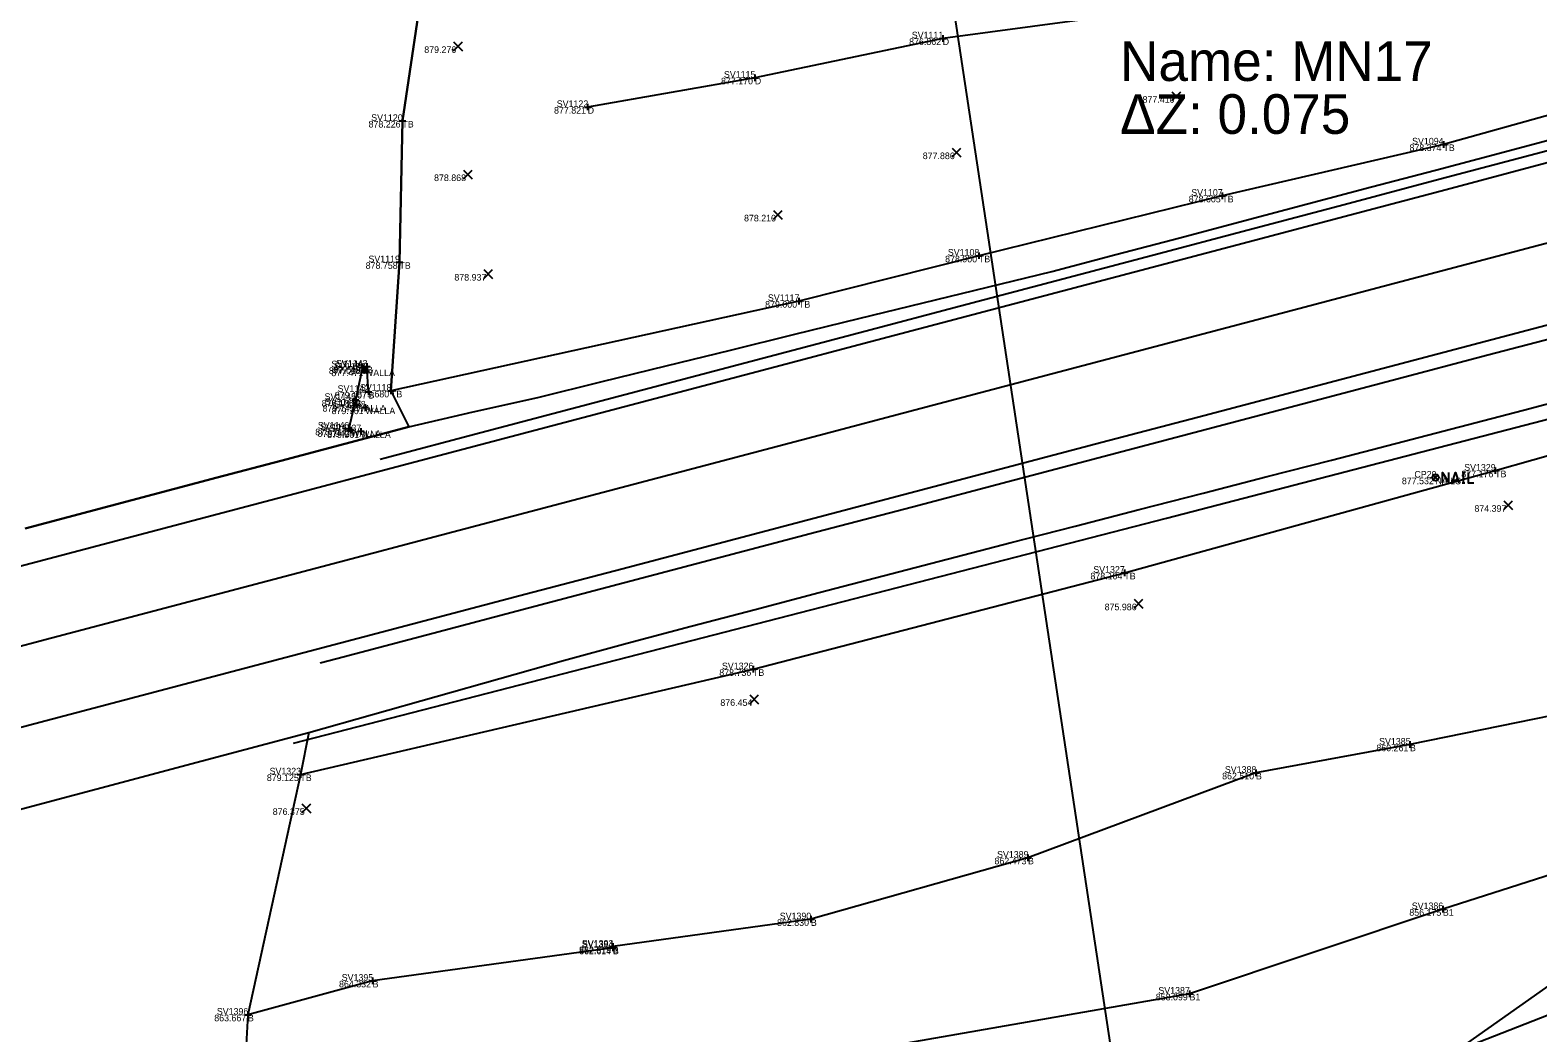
# Model space of a CAD drawing. Extents: x 2125299 to 2129212, y 713100 to 714300.
# Drawn here: x 2128033.5 to 2128261.4, y 713835.6 to 713987.2 of the extents above; entities that cross this region are included whole.
import ezdxf

# ---------------------------------------------------------------- set-up
doc = ezdxf.new("R2010")
doc.units = 0
for name, color, linetype in [('_CIVIL_CONSTRUCTION', 7, 'Continuous'), ('Default', 7, 'Continuous'), ('DR_X_Ditch', 7, 'Continuous'), ('DT_X_Void', 7, 'Continuous'), ('PV_X_EOP', 7, 'Continuous'), ('PV_X_Shoulder_Rumble_Strip', 7, 'Continuous'), ('RD_X_Fence', 7, 'Continuous'), ('RW_P_Esmt_TMP', 7, 'Continuous'), ('RW_X_CL_100_Curve_Data', 7, 'Continuous'), ('RW_X_Esmt_CH', 7, 'Continuous'), ('RW_X_Fee_WL', 7, 'Continuous'), ('SC_Scratch1', 7, 'Continuous'), ('SC_Scratch2', 7, 'Continuous'), ('SV_X_Break_Lines', 7, 'Continuous'), ('SV_X_Mon_Cells_Found', 7, 'Continuous'), ('SV_X_Text_Elevation', 7, 'Continuous'), ('SV_X_Text_Name', 7, 'Continuous'), ('SV_X_Top_of_Bank', 7, 'Continuous'), ('UT_X_Overhead_Telecom_FO', 7, 'Continuous')]:
    doc.layers.add(name, color=color, linetype=linetype)

msp = doc.modelspace()

# ---------------------------------------------------------------- linework, layer by layer
at = {"layer": '_CIVIL_CONSTRUCTION'}
msp.add_lwpolyline([(2128022.26, 713891.52), (2128036.76, 713895.35), (2128051.26, 713899.19), (2128065.76, 713903.02), (2128080.27, 713906.86), (2128094.77, 713910.69), (2128109.27, 713914.52), (2128123.77, 713918.35), (2128138.28, 713922.18), (2128152.78, 713926), (2128167.28, 713929.83), (2128181.79, 713933.66), (2128196.29, 713937.49), (2128210.79, 713941.32), (2128225.3, 713945.14), (2128239.8, 713948.97), (2128254.3, 713952.8), (2128268.81, 713956.63)], dxfattribs=at)
at = {"layer": 'Default'}
msp.add_lwpolyline([(2128027.32, 713868.17), (2128036.98, 713870.74), (2128046.65, 713873.31), (2128056.31, 713875.88), (2128065.98, 713878.44), (2128075.64, 713881.03), (2128074.37, 713874.69), (2128066.44, 713838.36), (2128065.59, 713822.89), (2128050.49, 713795.43), (2128103.72, 713804.69), (2128133.83, 713809.76), (2128180.68, 713818.15), (2128213.09, 713823.85), (2128249.08, 713832.87), (2128285.01, 713846.97)], dxfattribs=at)
at = {"layer": 'DR_X_Ditch'}
msp.add_lwpolyline([(2128539.96, 714065.48), (2128533.93, 714063.76), (2128504.91, 714054.76), (2128447.02, 714038.39), (2128399.37, 714025.09), (2128341.85, 714009.81), (2128283.6, 713994.68), (2128242.74, 713988.86), (2128205.78, 713990.56), (2128171.48, 713986), (2128143.07, 713980.05), (2128117.8, 713975.62)], dxfattribs=at)
at = {"layer": 'DT_X_Void'}
msp.add_lwpolyline([(2128091.1, 714003.39), (2128093.27, 713996.96), (2128089.79, 713973.52), (2128089.34, 713952.15), (2128088.07, 713932.71), (2128090.77, 713927.26), (2128081.1, 713924.7), (2128071.43, 713922.14), (2128061.77, 713919.58), (2128052.1, 713917.02), (2128042.43, 713914.46), (2128032.77, 713911.9)], dxfattribs=at)
at = {"layer": 'PV_X_EOP'}
for points in [[(2128032.77, 713911.9), (2128042.43, 713914.46), (2128052.1, 713917.02), (2128061.77, 713919.58), (2128071.43, 713922.14), (2128081.1, 713924.7), (2128090.77, 713927.26), (2128100.51, 713929.52), (2128110.27, 713931.7), (2128119.98, 713934.09), (2128129.69, 713936.48), (2128139.4, 713938.87), (2128149.11, 713941.25), (2128158.82, 713943.63), (2128168.53, 713946.01), (2128178.25, 713948.39), (2128187.96, 713950.77), (2128197.63, 713953.31), (2128207.3, 713955.86), (2128216.97, 713958.42), (2128226.63, 713960.98), (2128236.3, 713963.53), (2128245.97, 713966.09), (2128255.64, 713968.65), (2128265.3, 713971.22)], [(2128027.32, 713868.17), (2128036.98, 713870.74), (2128046.65, 713873.31), (2128056.31, 713875.88), (2128065.98, 713878.44), (2128075.64, 713881.03), (2128085.26, 713883.75), (2128094.88, 713886.47), (2128104.51, 713889.2), (2128114.13, 713891.92), (2128123.77, 713894.56), (2128133.44, 713897.11), (2128143.11, 713899.65), (2128152.78, 713902.2), (2128162.46, 713904.74), (2128172.14, 713907.24), (2128181.82, 713909.74), (2128191.5, 713912.24), (2128201.18, 713914.74), (2128210.87, 713917.24), (2128220.55, 713919.74), (2128230.23, 713922.24), (2128239.91, 713924.74), (2128249.6, 713927.24), (2128259.27, 713929.78), (2128268.94, 713932.34)]]:
    msp.add_lwpolyline(points, dxfattribs=at)
at = {"layer": 'PV_X_Shoulder_Rumble_Strip'}
for points in [[(2128086.42, 713922.37), (2128087.17, 713922.56), (2128101.67, 713926.39), (2128116.17, 713930.23), (2128130.67, 713934.06), (2128145.17, 713937.89), (2128159.68, 713941.72), (2128174.18, 713945.55), (2128188.68, 713949.38), (2128203.18, 713953.21), (2128217.68, 713957.05), (2128232.18, 713960.89), (2128246.68, 713964.74), (2128261.18, 713968.58), (2128275.68, 713972.42), (2128290.18, 713976.26), (2128304.68, 713980.1), (2128319.18, 713983.94), (2128333.68, 713987.78)], [(2128077.36, 713891.58), (2128079.87, 713892.24), (2128094.37, 713896.07), (2128108.87, 713899.89), (2128123.38, 713903.71), (2128137.88, 713907.53), (2128152.38, 713911.36), (2128166.89, 713915.18), (2128181.39, 713919), (2128195.9, 713922.83), (2128210.4, 713926.65), (2128224.91, 713930.47), (2128239.41, 713934.29), (2128253.91, 713938.12), (2128268.41, 713941.95)]]:
    msp.add_lwpolyline(points, dxfattribs=at)
at = {"layer": 'RD_X_Fence'}
msp.add_lwpolyline([(2128324.53, 713881.58), (2128301.55, 713867.57), (2128272.2, 713849.2), (2128249.08, 713832.87), (2128213.09, 713823.85), (2128180.68, 713818.15), (2128133.83, 713809.76), (2128103.72, 713804.69), (2128050.49, 713795.43)], dxfattribs=at)
at = {"layer": 'SC_Scratch1'}
msp.add_lwpolyline([(2128073.34, 713879.42), (2128205.29, 713913.45), (2128375.42, 713957.63), (2128480.61, 713986.26)], dxfattribs=at)
at = {"layer": 'SC_Scratch2'}
for points in [[(2128030.06, 713905.67), (2128044.56, 713909.5), (2128059.06, 713913.33), (2128073.57, 713917.16), (2128088.07, 713920.99), (2128102.57, 713924.83), (2128117.07, 713928.66), (2128131.57, 713932.49), (2128146.08, 713936.32), (2128160.58, 713940.15), (2128175.08, 713943.98), (2128189.58, 713947.82), (2128204.09, 713951.65), (2128218.59, 713955.49), (2128233.09, 713959.33), (2128247.59, 713963.17), (2128262.09, 713967.01), (2128276.59, 713970.85), (2128291.09, 713974.69), (2128305.59, 713978.53), (2128320.09, 713982.37), (2128334.59, 713986.21), (2128349.09, 713990.05)], [(2128021.45, 713879.04), (2128035.96, 713882.86), (2128050.46, 713886.69), (2128064.97, 713890.51), (2128079.47, 713894.33), (2128093.98, 713898.16), (2128108.48, 713901.98), (2128122.99, 713905.8), (2128137.49, 713909.62), (2128151.99, 713913.45), (2128166.5, 713917.27), (2128181, 713921.09), (2128195.51, 713924.92), (2128210.01, 713928.74), (2128224.52, 713932.56), (2128239.02, 713936.39), (2128253.53, 713940.21), (2128268.03, 713944.04)]]:
    msp.add_lwpolyline(points, dxfattribs=at)
at = {"layer": 'SV_X_Break_Lines'}
for points in [[(2128084.68, 713932.54), (2128084.42, 713936.37), (2128083.78, 713936.25), (2128082.7, 713931.33), (2128081.71, 713926.98)], [(2128473.37, 713923.91), (2128453.45, 713915.84), (2128410.19, 713893.98), (2128387.41, 713892.53), (2128363.21, 713893.72), (2128345.6, 713896.5), (2128318.82, 713891.26), (2128295.12, 713880.91), (2128274.49, 713885.8), (2128242.12, 713879.2), (2128218.83, 713874.94), (2128184.37, 713862.1), (2128151.55, 713852.79), (2128121.59, 713848.65), (2128121.63, 713848.49), (2128085.29, 713843.49), (2128066.44, 713838.36)], [(2128362.17, 713888.6), (2128349.08, 713887.91), (2128324.53, 713881.58), (2128301.55, 713867.57), (2128295.43, 713864.02), (2128280.27, 713864.93), (2128247.09, 713854.32), (2128208.78, 713841.53), (2128155.39, 713832.17), (2128105.37, 713824.74)]]:
    msp.add_lwpolyline(points, dxfattribs=at)
at = {"layer": 'SV_X_Mon_Cells_Found'}
for p, q in [((2128170.98, 713986), (2128171.98, 713986)), ((2128171.48, 713986.5), (2128171.48, 713985.5)), ((2128171.48, 713986), (2128171.48, 713986)), ((2128142.57, 713980.05), (2128143.57, 713980.05)), ((2128143.07, 713980.55), (2128143.07, 713979.55)), ((2128143.07, 713980.05), (2128143.07, 713980.05)), ((2128117.3, 713975.62), (2128118.3, 713975.62)), ((2128117.8, 713976.12), (2128117.8, 713975.12)), ((2128117.8, 713975.62), (2128117.8, 713975.62)), ((2128089.29, 713973.52), (2128090.29, 713973.52)), ((2128089.79, 713974.02), (2128089.79, 713973.02)), ((2128089.79, 713973.52), (2128089.79, 713973.52)), ((2128247.17, 713970.46), (2128247.17, 713969.46)), ((2128246.67, 713969.96), (2128247.67, 713969.96)), ((2128247.17, 713969.96), (2128247.17, 713969.96)), ((2128213.24, 713962.2), (2128214.24, 713962.2)), ((2128213.74, 713962.7), (2128213.74, 713961.7)), ((2128213.74, 713962.2), (2128213.74, 713962.2)), ((2128088.84, 713952.15), (2128089.84, 713952.15)), ((2128089.34, 713952.65), (2128089.34, 713951.65)), ((2128089.34, 713952.15), (2128089.34, 713952.15)), ((2128176.45, 713953.14), (2128177.45, 713953.14)), ((2128176.95, 713953.64), (2128176.95, 713952.64)), ((2128176.95, 713953.14), (2128176.95, 713953.14)), ((2128149.25, 713946.28), (2128150.25, 713946.28)), ((2128149.75, 713946.78), (2128149.75, 713945.78)), ((2128149.75, 713946.28), (2128149.75, 713946.28)), ((2128083.28, 713936.25), (2128084.28, 713936.25)), ((2128083.63, 713935.92), (2128084.63, 713935.92)), ((2128083.78, 713936.75), (2128083.78, 713935.75)), ((2128083.78, 713936.25), (2128083.78, 713936.25)), ((2128083.92, 713936.37), (2128084.92, 713936.37)), ((2128084.13, 713936.42), (2128084.13, 713935.42)), ((2128084.13, 713935.92), (2128084.13, 713935.92)), ((2128084.42, 713936.87), (2128084.42, 713935.87)), ((2128084.42, 713936.37), (2128084.42, 713936.37)), ((2128082.2, 713931.33), (2128083.2, 713931.33)), ((2128082.7, 713931.83), (2128082.7, 713930.83)), ((2128082.7, 713931.33), (2128082.7, 713931.33)), ((2128084.18, 713932.54), (2128085.18, 713932.54)), ((2128084.68, 713933.04), (2128084.68, 713932.04)), ((2128084.68, 713932.54), (2128084.68, 713932.54)), ((2128087.57, 713932.71), (2128088.57, 713932.71)), ((2128088.07, 713933.21), (2128088.07, 713932.21)), ((2128088.07, 713932.71), (2128088.07, 713932.71)), ((2128082.29, 713930.56), (2128083.29, 713930.56)), ((2128082.79, 713931.06), (2128082.79, 713930.06)), ((2128082.79, 713930.56), (2128082.79, 713930.56)), ((2128083.68, 713930.18), (2128084.68, 713930.18)), ((2128084.18, 713930.68), (2128084.18, 713929.68)), ((2128084.18, 713930.18), (2128084.18, 713930.18)), ((2128081.21, 713926.98), (2128082.21, 713926.98)), ((2128081.54, 713926.74), (2128082.54, 713926.74)), ((2128081.71, 713927.48), (2128081.71, 713926.48)), ((2128081.71, 713926.98), (2128081.71, 713926.98)), ((2128082.04, 713927.24), (2128082.04, 713926.24)), ((2128082.04, 713926.74), (2128082.04, 713926.74)), ((2128083.5, 713927.08), (2128083.5, 713926.08)), ((2128083, 713926.58), (2128084, 713926.58)), ((2128083.5, 713926.58), (2128083.5, 713926.58)), ((2128254.49, 713920.63), (2128255.49, 713920.63)), ((2128254.99, 713921.13), (2128254.99, 713920.13)), ((2128254.99, 713920.63), (2128254.99, 713920.63)), ((2128198.44, 713905.19), (2128199.44, 713905.19)), ((2128198.94, 713905.69), (2128198.94, 713904.69)), ((2128198.94, 713905.19), (2128198.94, 713905.19)), ((2128142.3, 713890.6), (2128143.3, 713890.6)), ((2128142.8, 713891.1), (2128142.8, 713890.1)), ((2128142.8, 713890.6), (2128142.8, 713890.6)), ((2128241.62, 713879.2), (2128242.62, 713879.2)), ((2128242.12, 713879.7), (2128242.12, 713878.7)), ((2128242.12, 713879.2), (2128242.12, 713879.2)), ((2128073.87, 713874.69), (2128074.87, 713874.69)), ((2128074.37, 713875.19), (2128074.37, 713874.19)), ((2128074.37, 713874.69), (2128074.37, 713874.69)), ((2128218.33, 713874.94), (2128219.33, 713874.94)), ((2128218.83, 713875.44), (2128218.83, 713874.44)), ((2128218.83, 713874.94), (2128218.83, 713874.94)), ((2128183.87, 713862.1), (2128184.87, 713862.1)), ((2128184.37, 713862.6), (2128184.37, 713861.6)), ((2128184.37, 713862.1), (2128184.37, 713862.1)), ((2128246.59, 713854.32), (2128247.59, 713854.32)), ((2128247.09, 713854.82), (2128247.09, 713853.82)), ((2128247.09, 713854.32), (2128247.09, 713854.32)), ((2128151.05, 713852.79), (2128152.05, 713852.79)), ((2128151.55, 713853.29), (2128151.55, 713852.29)), ((2128151.55, 713852.79), (2128151.55, 713852.79)), ((2128121.09, 713848.65), (2128122.09, 713848.65)), ((2128121.13, 713848.49), (2128122.13, 713848.49)), ((2128121.59, 713849.15), (2128121.59, 713848.15)), ((2128121.59, 713848.65), (2128121.59, 713848.65)), ((2128121.63, 713848.99), (2128121.63, 713847.99)), ((2128121.63, 713848.49), (2128121.63, 713848.49)), ((2128084.79, 713843.49), (2128085.79, 713843.49)), ((2128085.29, 713843.99), (2128085.29, 713842.99)), ((2128085.29, 713843.49), (2128085.29, 713843.49)), ((2128208.28, 713841.53), (2128209.28, 713841.53)), ((2128208.78, 713842.03), (2128208.78, 713841.03)), ((2128208.78, 713841.53), (2128208.78, 713841.53)), ((2128065.94, 713838.36), (2128066.94, 713838.36)), ((2128066.44, 713838.86), (2128066.44, 713837.86)), ((2128066.44, 713838.36), (2128066.44, 713838.36))]:
    msp.add_line(p, q, dxfattribs=at)
at = {"layer": 'SV_X_Text_Elevation'}
for p, q in [((2128097.53, 713984.13), (2128098.87, 713985.46)), ((2128097.53, 713985.46), (2128098.87, 713984.13)), ((2128206.14, 713976.59), (2128207.47, 713977.93)), ((2128206.14, 713977.93), (2128207.47, 713976.59)), ((2128172.9, 713968.07), (2128174.23, 713969.41)), ((2128172.9, 713969.41), (2128174.23, 713968.07)), ((2128099.02, 713964.75), (2128100.35, 713966.09)), ((2128099.02, 713966.09), (2128100.35, 713964.75)), ((2128145.89, 713958.65), (2128147.22, 713959.99)), ((2128145.89, 713959.99), (2128147.22, 713958.65)), ((2128102.08, 713949.7), (2128103.41, 713951.04)), ((2128102.08, 713951.04), (2128103.41, 713949.7)), ((2128256.29, 713914.74), (2128257.62, 713916.08)), ((2128256.29, 713916.08), (2128257.62, 713914.74)), ((2128200.4, 713899.85), (2128201.74, 713901.19)), ((2128200.4, 713901.19), (2128201.74, 713899.85)), ((2128142.31, 713885.39), (2128143.65, 713886.72)), ((2128142.31, 713886.72), (2128143.65, 713885.39)), ((2128074.59, 713868.9), (2128075.93, 713870.24)), ((2128074.59, 713870.24), (2128075.93, 713868.9))]:
    msp.add_line(p, q, dxfattribs=at)
at = {"layer": 'SV_X_Text_Name'}
for p, q in [((2128245.61, 713919.93), (2128246.32, 713919.23)), ((2128245.61, 713919.23), (2128246.32, 713919.93))]:
    msp.add_line(p, q, dxfattribs=at)
for points in [[(2128247.06, 713918.77), (2128247.06, 713920.37), (2128248, 713918.77), (2128248, 713920.37)], [(2128248.51, 713918.77), (2128249.01, 713920.37), (2128249.5, 713918.77)], [(2128250.01, 713920.37), (2128250.41, 713920.37)], [(2128250.21, 713918.77), (2128250.21, 713920.37)], [(2128250.91, 713920.37), (2128250.91, 713918.77), (2128251.78, 713918.77)], [(2128249.38, 713919.15), (2128248.63, 713919.15)], [(2128250.01, 713918.77), (2128250.41, 713918.77)]]:
    msp.add_lwpolyline(points, dxfattribs=at)
msp.add_circle((2128245.97, 713919.58), 0.5, dxfattribs=at)
at = {"layer": 'SV_X_Top_of_Bank'}
for points in [[(2128641.06, 714074.44), (2128591.12, 714062.19), (2128554.7, 714051.88), (2128508.37, 714039.66), (2128452.53, 714024.9), (2128402.4, 714011.79), (2128346.92, 713996.07), (2128287.48, 713981.18), (2128247.17, 713969.96), (2128213.74, 713962.2), (2128176.95, 713953.14), (2128149.75, 713946.28), (2128088.07, 713932.71), (2128089.34, 713952.15), (2128089.79, 713973.52), (2128093.27, 713996.96)], [(2128074.37, 713874.69), (2128142.8, 713890.6), (2128198.94, 713905.19), (2128254.99, 713920.63), (2128306.24, 713935.17), (2128365.05, 713950.7), (2128425.17, 713967.42), (2128484.19, 713980.57), (2128536.73, 713996.44), (2128593.25, 714009.66)]]:
    msp.add_lwpolyline(points, dxfattribs=at)
at = {"layer": 'UT_X_Overhead_Telecom_FO'}
msp.add_lwpolyline([(2128144.62, 714178.88), (2128199.4, 713816.51)], dxfattribs=at)

# ---------------------------------------------------------------- texts
at = {"layer": '_CIVIL_CONSTRUCTION'}
for s, p in [('Name: MN17', (2128198.3, 713979.56)), ('ΔZ: 0.075', (2128198.3, 713971.56))]:
    msp.add_text(s, height=6, dxfattribs=at).set_placement(p)
at = {"layer": 'RW_P_Esmt_TMP'}
for s, p in [('D', (2128171.48, 713985)), ('D', (2128143.07, 713979.05)), ('D', (2128117.8, 713974.62)), ('TB', (2128089.79, 713972.52)), ('TB', (2128247.17, 713968.96)), ('TB', (2128213.74, 713961.2)), ('TB', (2128089.34, 713951.15)), ('TB', (2128176.95, 713952.14)), ('TB', (2128149.75, 713945.28)), ('B', (2128083.78, 713935.25)), ('B', (2128084.42, 713935.37)), ('B', (2128082.7, 713930.33)), ('B', (2128084.68, 713931.54)), ('TB', (2128088.07, 713931.71)), ('B', (2128081.71, 713925.98)), ('TB', (2128254.99, 713919.63)), ('NAILS', (2128245.97, 713918.58)), ('TB', (2128198.94, 713904.19)), ('TB', (2128142.8, 713889.6)), ('B', (2128242.12, 713878.2)), ('TB', (2128074.37, 713873.69)), ('B', (2128218.83, 713873.94)), ('B', (2128184.37, 713861.1)), ('B1', (2128247.09, 713853.32)), ('B', (2128151.55, 713851.79)), ('B', (2128121.59, 713847.65)), ('B', (2128121.63, 713847.49)), ('B', (2128085.29, 713842.49)), ('B1', (2128208.78, 713840.53)), ('B', (2128066.44, 713837.36))]:
    msp.add_text(s, height=1, dxfattribs=at).set_placement(p)
at = {"layer": 'RW_X_CL_100_Curve_Data'}
for s, p in [('877.471', (2128079.05, 713934.92)), ('SV1139', (2128079.45, 713935.92)), ('WALLA', (2128084.13, 713934.92)), ('SV1140', (2128078.08, 713930.56)), ('879.745', (2128077.72, 713929.56)), ('879.761', (2128079.09, 713929.18)), ('SV1138', (2128079.48, 713930.18)), ('WALLA', (2128082.79, 713929.56)), ('WALLA', (2128084.18, 713929.18)), ('879.942', (2128076.97, 713925.74)), ('SV1141', (2128077.36, 713926.74)), ('SV1137', (2128078.81, 713926.58)), ('WALLA', (2128082.04, 713925.74)), ('879.901', (2128078.42, 713925.58)), ('WALLA', (2128083.5, 713925.58))]:
    msp.add_text(s, height=1, dxfattribs=at).set_placement(p)
at = {"layer": 'RW_X_Esmt_CH'}
for s, p in [('SV1111', (2128166.8, 713986)), ('SV1115', (2128138.4, 713980.05)), ('SV1122', (2128113.13, 713975.62)), ('SV1120', (2128085.08, 713973.52)), ('SV1094', (2128242.44, 713969.96)), ('SV1107', (2128209.05, 713962.2)), ('SV1108', (2128172.25, 713953.14)), ('SV1119', (2128084.66, 713952.15)), ('SV1117', (2128145.05, 713946.28)), ('SV1144', (2128079.06, 713936.25)), ('SV1143', (2128079.75, 713936.37)), ('SV1142', (2128080, 713932.54)), ('SV1118', (2128083.37, 713932.71)), ('SV1145', (2128078.03, 713931.33)), ('SV1146', (2128077.01, 713926.98)), ('CP20', (2128242.79, 713919.58)), ('SV1329', (2128250.31, 713920.63)), ('SV1327', (2128194.24, 713905.19)), ('SV1326', (2128138.1, 713890.6)), ('SV1385', (2128237.45, 713879.2)), ('SV1323', (2128069.71, 713874.69)), ('SV1388', (2128214.13, 713874.94)), ('SV1389', (2128179.69, 713862.1)), ('SV1390', (2128146.84, 713852.79)), ('SV1386', (2128242.39, 713854.32)), ('SV1394', (2128116.91, 713848.49)), ('SV1393', (2128116.93, 713848.65)), ('SV1395', (2128080.62, 713843.49)), ('SV1387', (2128204.08, 713841.53)), ('SV1396', (2128061.74, 713838.36))]:
    msp.add_text(s, height=1, dxfattribs=at).set_placement(p)
at = {"layer": 'RW_X_Fee_WL'}
for s, p in [('876.862', (2128166.4, 713985)), ('879.276', (2128093.1, 713983.8)), ('877.170', (2128137.96, 713979.05)), ('877.410', (2128201.69, 713976.26)), ('877.821', (2128112.72, 713974.62)), ('878.226', (2128084.68, 713972.52)), ('877.886', (2128168.46, 713967.74)), ('878.374', (2128242.04, 713968.96)), ('878.868', (2128094.58, 713964.42)), ('878.605', (2128208.67, 713961.2)), ('878.210', (2128141.44, 713958.32)), ('878.758', (2128084.24, 713951.15)), ('878.900', (2128171.84, 713952.14)), ('878.937', (2128097.65, 713949.37)), ('879.000', (2128144.63, 713945.28)), ('877.038', (2128078.68, 713935.25)), ('877.401', (2128079.33, 713935.37)), ('876.136', (2128077.59, 713930.33)), ('879.107', (2128079.58, 713931.54)), ('879.680', (2128082.96, 713931.71)), ('875.717', (2128076.62, 713925.98)), ('877.176', (2128249.88, 713919.63)), ('877.532', (2128240.89, 713918.58)), ('874.397', (2128251.86, 713914.41)), ('878.104', (2128193.81, 713904.19)), ('875.986', (2128195.96, 713899.52)), ('878.736', (2128137.7, 713889.6)), ('876.454', (2128137.86, 713885.06)), ('860.261', (2128237.04, 713878.2)), ('879.125', (2128069.3, 713873.69)), ('862.510', (2128213.72, 713873.94)), ('876.375', (2128070.19, 713868.57)), ('862.473', (2128179.3, 713861.1)), ('856.175', (2128242.02, 713853.32)), ('862.830', (2128146.43, 713851.79)), ('862.619', (2128116.51, 713847.65)), ('862.614', (2128116.51, 713847.49)), ('864.332', (2128080.21, 713842.49)), ('858.099', (2128203.69, 713840.53)), ('863.667', (2128061.35, 713837.36))]:
    msp.add_text(s, height=1, dxfattribs=at).set_placement(p)

doc.saveas('drawing.dxf')
